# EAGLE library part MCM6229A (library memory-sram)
MEMORY
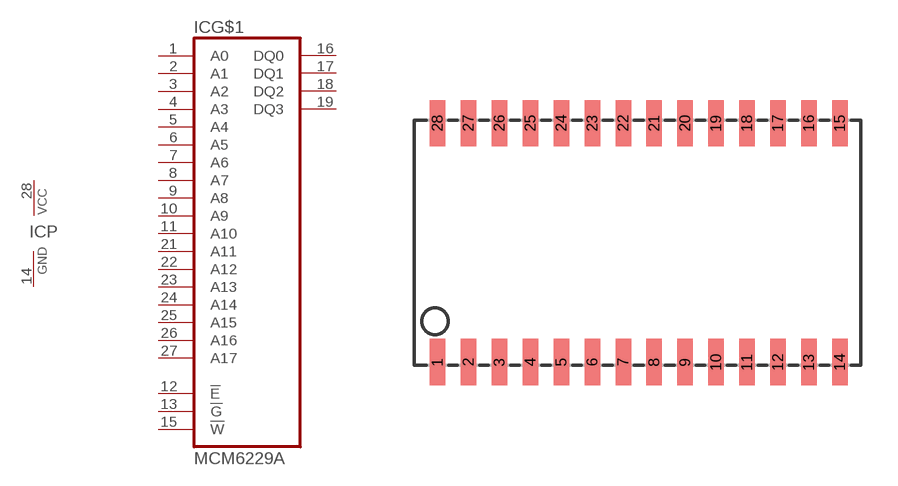
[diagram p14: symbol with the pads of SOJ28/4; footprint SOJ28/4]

Designator prefix IC; gates G$1=CM6229A P=PWRN

## MCM6229A  [SOJ28/4]
1  G$1:A0  in
2  G$1:A1  in
3  G$1:A2  in
4  G$1:A3  in
5  G$1:A4  in
6  G$1:A5  in
7  G$1:A6  in
8  G$1:A7  in
9  G$1:A8  in
10  G$1:A9  in
11  G$1:A10  in
12  G$1:!E  in
13  G$1:!G  in
14  P:GND  pwr
15  G$1:!W  in
16  G$1:DQ0
17  G$1:DQ1
18  G$1:DQ2
19  G$1:DQ3
21  G$1:A11  in
22  G$1:A12  in
23  G$1:A13  in
24  G$1:A14  in
25  G$1:A15  in
26  G$1:A16  in
27  G$1:A17  in
28  P:VCC  pwr

## Footprint SOJ28/4 (pad centres in mm)
Small Outline J-Bend
smd 0.635 x 1.905: 1 -8.255,-4.902; 2 -6.985,-4.902; 3 -5.715,-4.902; 4 -4.445,-4.902; 5 -3.175,-4.902; 6 -1.905,-4.902; 7 -0.635,-4.902; 8 0.635,-4.902; 9 1.905,-4.902; 10 3.175,-4.902; 11 4.445,-4.902; 12 5.715,-4.902; 13 6.985,-4.902; 14 8.255,-4.902; 15 8.255,4.902; 16 6.985,4.902; 17 5.715,4.902; 18 4.445,4.902; 19 3.175,4.902; 20 1.905,4.902; 21 0.635,4.902; 22 -0.635,4.902; 23 -1.905,4.902; 24 -3.175,4.902; 25 -4.445,4.902; 26 -5.715,4.902; 27 -6.985,4.902; 28 -8.255,4.902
